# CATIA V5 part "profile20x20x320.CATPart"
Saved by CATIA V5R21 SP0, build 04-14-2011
Part number: profile 20x20x320
Bounding box of the stored display mesh (mm): x -24.289 to -4.289, y -1.335 to 18.665, z 0 to 320
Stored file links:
  C:\Users\2027.DESARCY-LEMIE30\Desktop\V14(17.02.2023)\profile20x20x320.CATPart
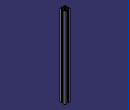
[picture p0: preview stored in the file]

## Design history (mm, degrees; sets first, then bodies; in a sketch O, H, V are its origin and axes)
Body1 (main body)
  Sketch1 on xy-plane, origin (0, 0, 0), H (1, 0, 0), V (0, 1, 0)
    point P1 (-17.2892, 11.6647)
    line L1 (-16.2892, 11.6647) -> (-12.2892, 11.6647)
    point P2 (-11.2892, 11.6647)
    line L2 (-11.2892, 10.6647) -> (-11.2892, 6.6647)
    point P3 (-11.2892, 5.6647)
    line L3 (-12.2892, 5.6647) -> (-16.2892, 5.6647)
    point P4 (-17.2892, 5.6647)
    line L4 (-17.2892, 6.6647) -> (-17.2892, 10.6647)
    point P5 (-24.2892, 18.6647)
    point P6 (-4.2892, 18.6647)
    point P7 (-4.2892, -1.3353)
    line L5 (-11.1892, 18.6647) -> (-11.1892, 16.6647)
    point P8 (-11.1892, 18.6647)
    point P10 (-11.1892, 18.6647)
    point P11 (-17.3892, 18.6647)
    line L6 (-17.3892, 18.6647) -> (-17.3892, 16.6647)
    point P12 (-17.3892, 18.6647)
    line L7 (-11.1892, 18.6647) -> (-4.2892, 18.6647)
    point P14 (-11.1892, 18.6647)
    point P15 (-4.2892, 18.6647)
    point P16 (-11.1892, -1.3353)
    point P17 (-17.3892, -1.3353)
    line L8 (-17.3892, -1.3353) -> (-17.3892, 0.6647)
    point P18 (-17.3892, -1.3353)
    line L9 (-11.1892, -1.3353) -> (-11.1892, 0.6647)
    point P20 (-11.1892, -1.3353)
    line L10 (-24.2892, -1.3353) -> (-17.3892, -1.3353)
    point P22 (-24.2892, -1.3353)
    point P23 (-17.3892, -1.3353)
    line L11 (-11.1892, -1.3353) -> (-4.2892, -1.3353)
    point P24 (-11.1892, -1.3353)
    point P25 (-4.2892, -1.3353)
    line L12 (-24.2892, 18.6647) -> (-17.3892, 18.6647)
    point P26 (-24.2892, 18.6647)
    point P27 (-17.3892, 18.6647)
    point P28 (-4.2892, 5.5647)
    point P29 (-4.2892, 11.7647)
    line L13 (-6.2892, 11.7647) -> (-4.2892, 11.7647)
    point P31 (-4.2892, 11.7647)
    line L14 (-4.2892, 5.5647) -> (-6.2892, 5.5647)
    point P32 (-4.2892, 5.5647)
    point P34 (-24.2892, 5.5647)
    point P35 (-24.2892, 11.7647)
    line L15 (-24.2892, 11.7647) -> (-22.2892, 11.7647)
    point P36 (-24.2892, 11.7647)
    line L16 (-24.2892, 5.5647) -> (-22.2892, 5.5647)
    point P38 (-24.2892, 5.5647)
    line L17 (-4.2892, 18.6647) -> (-4.2892, 11.7647)
    point P40 (-4.2892, 18.6647)
    point P41 (-4.2892, 11.7647)
    line L18 (-24.2892, 18.6647) -> (-24.2892, 11.7647)
    point P42 (-24.2892, 18.6647)
    point P43 (-24.2892, 11.7647)
    line L19 (-24.2892, -1.3353) -> (-24.2892, 5.5647)
    point P44 (-24.2892, -1.3353)
    point P45 (-24.2892, 5.5647)
    line L20 (-4.2892, -1.3353) -> (-4.2892, 5.5647)
    point P46 (-4.2892, -1.3353)
    point P47 (-4.2892, 5.5647)
    line L21 (-22.2892, 5.5647) -> (-22.2892, 1.6647)
    line L22 (-21.2892, 0.6647) -> (-17.3892, 0.6647)
    line L23 (-6.2892, 5.5647) -> (-6.2892, 1.6647)
    line L24 (-11.1892, 0.6647) -> (-7.2892, 0.6647)
    line L25 (-11.1892, 16.6647) -> (-7.2892, 16.6647)
    line L26 (-6.2892, 15.6647) -> (-6.2892, 11.7647)
    line L27 (-17.3892, 16.6647) -> (-21.2892, 16.6647)
    line L28 (-22.2892, 15.6647) -> (-22.2892, 11.7647)
    point P48 (-16.2892, 11.6647)
    point P49 (-17.2892, 10.6647)
    point P50 (-17.2892, 6.6647)
    point P52 (-11.2892, 6.6647)
    point P53 (-11.2892, 10.6647)
    point P54 (-12.2892, 11.6647)
    point P55 (-12.2892, 5.6647)
    line L29 (-16.2892, 11.6647) -> (-21.2892, 16.6647)
    line L30 (-17.2892, 10.6647) -> (-22.2892, 15.6647)
    line L31 (-12.2892, 11.6647) -> (-7.2892, 16.6647)
    line L32 (-16.2892, 5.6647) -> (-21.2892, 0.6647)
    line L33 (-17.2892, 6.6647) -> (-22.2892, 1.6647)
    line L34 (-12.2892, 5.6647) -> (-7.2892, 0.6647)
    line L35 (-11.2892, 6.6647) -> (-6.2892, 1.6647)
    line L36 (-11.2892, 10.6647) -> (-6.2892, 15.6647)
    length L5 = 2
    distance P10 P6 = 6.9
    length L6 = 2
    length L8 = 2
    length L9 = 2
    distance P7 P28 = 6.9
    distance P6 P29 = 6.9
    length L13 = 2
    length L14 = 2
    length L15 = 2
    distance P5 P42 = 0
    length L11 = 6.9
    distance P46 P7 = 0
    distance P1 P48 = 1
    distance P49 P1 = 1
    distance P4 P50 = 1
    distance P54 P2 = 1
    distance P2 P3 = 6
    distance P1 P2 = 6
    horizontal: L1 H, L3 H, L7 H, L10 H, L11 H, L12 H, L13 H, L14 H, L15 H, L16 H, L22 H, L24 H, L25 H, L27 H
    vertical: L2 V, L4 V, L5 V, L6 V, L8 V, L9 V, L17 V, L18 V, L19 V, L20 V, L21 V, L23 V, L26 V, L28 V
    coincidence: P10 P8, P11 P12, P6 P15, P8 P14, P16 L5, P17 L6, P17 P18, P16 P20, P23 L8, P24 L9, P20 P24, P27 L6, P5 P26, P29 P31, P28 P32, P34 L14, P35 L13, P34 P38, P35 P36, P40 L7, P41 L13, P6 P40, P42 L7, P43 L13, P44 L11, P45 L14, P38 P45, P46 L11, P47 L14, P49 L4, P50 L4, P52 L2, P53 L2, P55 L3, P22 P44, P25 P46
    fix: P34, P12, P5, P36, P55
  Pad1: profile Sketch1, direction (0, 0, 1), length 320
  Sketch2 on end face of Pad1, origin (0, 0, 320), H (1, 0, 0), V (0, 1, 0)
    circle A1 centre (-14.2892, 8.6647) radius 2.5
    point P1 (-14.2892, 8.6647)
    reference projected line E1 (-12.2892, 11.6647) -> (-16.2892, 11.6647) from edge [face of Pad1 from Sketch1.L1 | end face of Pad1]
    reference projected line E2 (-11.2892, 6.6647) -> (-11.2892, 10.6647) from edge [face of Pad1 from Sketch1.L2 | end face of Pad1]
    radius A1 = 2.5
    distance P1 E1 = 3
    distance P1 E2 = 3
  Pocket1: profile Sketch2, direction (0, 0, -1), length 320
